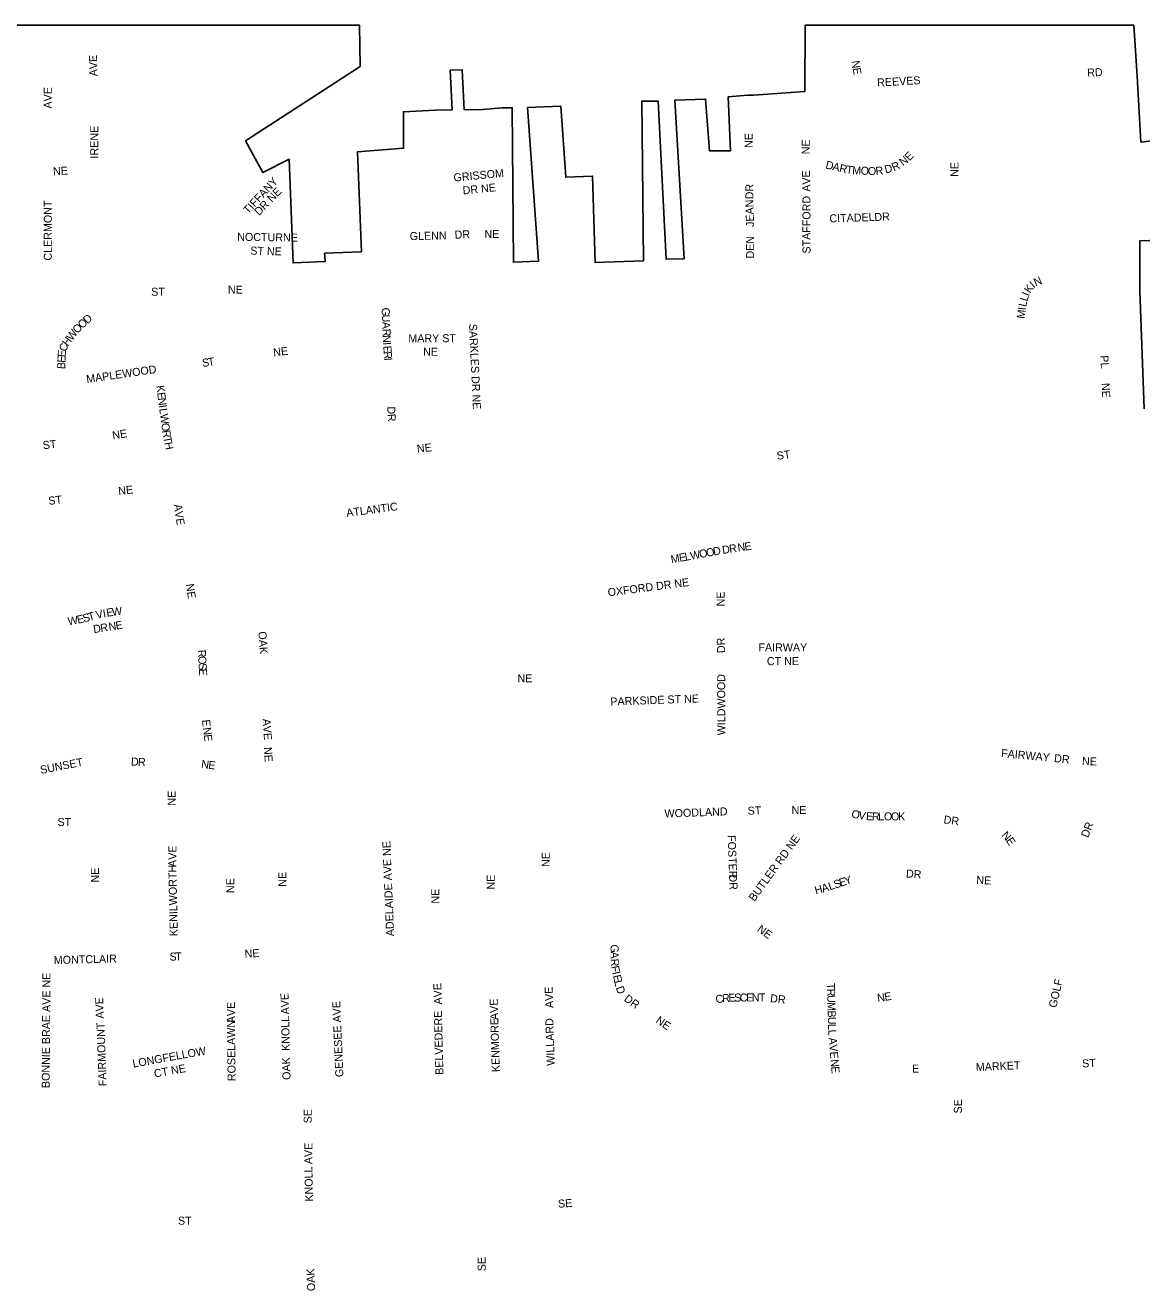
# Model space of a CAD drawing. Extents: x 0 to 34, y -0.1 to 32.4.
# Drawn here: x 4.363 to 5.683, y 30.861 to 32.359 of the extents above; entities that cross this region are included whole.
import ezdxf

# ---------------------------------------------------------------- set-up
doc = ezdxf.new("R2010")
doc.units = 0
doc.layers.add('GM_X_Interchange_Ramps', color=7, linetype='Continuous')
doc.layers.add('GM_X_US_Shield', color=7, linetype='Continuous')

msp = doc.modelspace()

# ---------------------------------------------------------------- linework, layer by layer
at = {"layer": 'GM_X_Interchange_Ramps'}
for p, q in [((4.7582, 32.3588), (4.09, 32.3588)), ((5.6741, 32.3588), (5.2853, 32.3588))]:
    msp.add_line(p, q, dxfattribs=at)
for points in [[(5.2853, 32.3588), (5.2849, 32.2804), (5.2245, 32.2763), (5.2175, 32.2763), (5.1943, 32.2742), (5.197, 32.2104), (5.1723, 32.2104), (5.1676, 32.2716), (5.1312, 32.2703), (5.142, 32.0826), (5.1208, 32.082), (5.1116, 32.269), (5.092, 32.2692), (5.0939, 32.0801), (5.0367, 32.0782), (5.0339, 32.1803), (5.0021, 32.1791), (4.9961, 32.2631), (4.9567, 32.2615), (4.9697, 32.0799), (4.9401, 32.0784), (4.9389, 32.2613), (4.9264, 32.2612), (4.9041, 32.2592), (4.8819, 32.2589), (4.8797, 32.3063), (4.8655, 32.3056), (4.8676, 32.2588), (4.8475, 32.2583), (4.8101, 32.2565), (4.8103, 32.2133), (4.7558, 32.2091), (4.7604, 32.0908), (4.7168, 32.0891), (4.717, 32.0858), (4.7174, 32.0792), (4.6796, 32.0777), (4.6748, 32.2004), (4.6436, 32.1848), (4.6234, 32.2221), (4.759, 32.3101), (4.7582, 32.3588)], [(5.7691, 32.2312), (5.6825, 32.2207), (5.678, 32.2988), (5.6741, 32.3588)], [(5.6863, 31.9049), (5.6813, 32.0448), (5.6813, 32.1036), (5.7604, 32.1065)]]:
    msp.add_lwpolyline(points, dxfattribs=at)

# ---------------------------------------------------------------- texts
at = {"layer": 'GM_X_US_Shield'}
for s, rotation, p in [('AVE', 91.468, (4.4482, 32.2986)), ('N', 278.1363, (5.3401, 32.3164)), ('E', 279.924, (5.3414, 32.3078)), ('REEVES', 3.3023, (5.3707, 32.2863)), ('RD', 3.0116, (5.6191, 32.298)), ('AVE', 90, (4.3941, 32.2603)), ('IRENE', 90, (4.4491, 32.2012)), ('NE', 90, (5.2232, 32.2137)), ('NE', 90, (5.2907, 32.2062)), ('E', 43.7058, (5.4084, 32.1977)), ('D', 346.4779, (5.3088, 32.1896)), ('A', 346.4779, (5.3169, 32.1876)), ('R', 346.4703, (5.325, 32.1857)), ('T', 351.9836, (5.3333, 32.1837)), ('D', 15.3226, (5.3806, 32.1833)), ('R', 24.6002, (5.3902, 32.186)), ('N', 38.2023, (5.4011, 32.1919)), ('NE', 90, (5.4666, 32.1795)), ('NE', 3.011, (4.3958, 32.1813)), ('TIFFANY', 47.0689, (4.6264, 32.1348)), ('GRISSOM', 5.528, (4.8698, 32.1738)), ('AVE', 91.5062, (5.2916, 32.162)), ('M', 357.1643, (5.3408, 32.1827)), ('O', 357.2682, (5.3508, 32.1822)), ('O', 358.2026, (5.3593, 32.1818)), ('R', 6.6567, (5.3691, 32.1816)), ('DR NE', 46.0045, (4.6394, 32.133)), ('DR NE', 5.5717, (4.8806, 32.1586)), ('DR', 90, (5.2241, 32.1529)), ('CLERMONT', 90, (4.3941, 32.0804)), ('JEAN', 91.6837, (5.2249, 32.1203)), ('STAFFORD', 90, (5.2916, 32.0887)), ('CITADEL', 1.9405, (5.3141, 32.1255)), ('DR', 3.011, (5.3674, 32.1271)), ('NOCTURNE', 359.2466, (4.6134, 32.1038)), ('GLENN', 1.1711, (4.8176, 32.1046)), ('DR', 1.9739, (4.8708, 32.1063)), ('NE', 0, (4.9059, 32.1071)), ('DEN', 90, (5.2249, 32.0828)), ('ST NE', 358.4935, (4.6288, 32.0875)), ('N', 23.6119, (5.5581, 32.0497)), ('ST', 0, (4.5117, 32.0388)), ('NE', 0, (4.6025, 32.0413)), ('I', 68.6126, (5.5499, 32.0377)), ('K', 54.7519, (5.5512, 32.041)), ('I', 40.561, (5.5556, 32.0474)), ('L', 77.246, (5.5466, 32.0251)), ('L', 72.8049, (5.548, 32.0315)), ('D', 42.7897, (4.4363, 32.0049)), ('G', 272.2517, (4.7843, 32.0246)), ('U', 272.2526, (4.7846, 32.0163)), ('M', 83.1167, (5.5449, 32.0113)), ('I', 83.1419, (5.5461, 32.0213)), ('W', 52.7686, (4.418, 31.985)), ('O', 45.0464, (4.4243, 31.9934)), ('O', 42.8354, (4.4301, 31.9993)), ('A', 272.2526, (4.785, 32.0079)), ('R', 272.2558, (4.7853, 31.9996)), ('SARKLES DR NE', 272.7012, (4.8876, 32.0054)), ('H', 54.5335, (4.4132, 31.9783)), ('N', 272.4218, (4.7856, 31.9921)), ('I', 273.4139, (4.7859, 31.9836)), ('MARY ST', 0, (4.8159, 31.9838)), ('E', 86.7194, (4.4105, 31.966)), ('C', 67.9145, (4.4107, 31.9719)), ('NE', 6.0054, (4.6565, 31.9671)), ('E', 274.2622, (4.7862, 31.9793)), ('R', 274.412, (4.7867, 31.9726)), ('NE', 0, (4.8334, 31.9677)), ('B', 88.0326, (4.4099, 31.9519)), ('E', 87.349, (4.4102, 31.9594)), ('MAPLEWOOD', 8.3105, (4.4356, 31.9354)), ('S', 5.7595, (4.5724, 31.9546)), ('T', 9.0724, (4.5796, 31.9554)), ('I', 274.4275, (4.7873, 31.9651)), ('PL', 273.5742, (5.6343, 31.968)), ('K', 277.5629, (4.5176, 31.9322)), ('E', 277.5351, (4.5187, 31.924)), ('NE', 273.0113, (5.6359, 31.9354)), ('N', 277.5526, (4.5196, 31.9174)), ('I', 277.5837, (4.5207, 31.9091)), ('L', 277.5622, (4.5212, 31.905)), ('W', 277.5535, (4.5221, 31.8984)), ('D', 270.2841, (4.791, 31.9078)), ('R', 275.2278, (4.7911, 31.8986)), ('NE', 8.9729, (4.4664, 31.8688)), ('O', 277.5412, (4.5235, 31.8876)), ('R', 279.3459, (4.5247, 31.8791)), ('ST', 6.5823, (4.384, 31.8571)), ('T', 280.7822, (4.5259, 31.8714)), ('H', 280.8955, (4.5272, 31.8648)), ('NE', 6.0123, (4.8265, 31.853)), ('ST', 7.598, (5.2523, 31.8446)), ('NE', 6.0123, (4.4732, 31.803)), ('ST', 6.5823, (4.3906, 31.7913)), ('AVE', 278.7466, (4.5384, 31.7915)), ('ATLANTIC', 7.4322, (4.7431, 31.7771)), ('D', 8.988, (5.1878, 31.7332)), ('R', 8.1885, (5.196, 31.7345)), ('N', 8.1356, (5.2059, 31.736)), ('E', 8.1317, (5.2141, 31.7371)), ('M', 10.4295, (5.1272, 31.7221)), ('E', 10.4233, (5.137, 31.7239)), ('L', 10.4367, (5.1436, 31.7251)), ('W', 10.4296, (5.1502, 31.7263)), ('O', 10.429, (5.1608, 31.7283)), ('O', 10.429, (5.169, 31.7298)), ('D', 10.429, (5.1772, 31.7313)), ('OXFORD DR NE', 7.3337, (5.0523, 31.683)), ('NE', 278.9682, (4.5526, 31.6973)), ('NE', 90, (5.1899, 31.6712)), ('E', 8.3754, (4.4593, 31.6589)), ('W', 6.9436, (4.4658, 31.6599)), ('W', 9.5867, (4.4139, 31.6488)), ('E', 12.1119, (4.425, 31.6507)), ('S', 15.1533, (4.4321, 31.6522)), ('T', 15.3055, (4.4385, 31.6539)), ('V', 13.2199, (4.4473, 31.6563)), ('I', 9.5054, (4.4553, 31.6582)), ('E', 8.7347, (4.4703, 31.6437)), ('D', 9.0311, (4.4439, 31.6395)), ('R', 9.0429, (4.4522, 31.6408)), ('N', 9.0096, (4.462, 31.6424)), ('OAK', 273.8119, (4.6385, 31.6413)), ('DR', 91.9739, (5.1907, 31.6161)), ('FAIRWAY', 0, (5.23, 31.618)), ('R', 273.4021, (4.5668, 31.6196)), ('O', 273.4217, (4.5672, 31.6121)), ('CT NE', 0, (5.24, 31.6017)), ('S', 273.4299, (4.5677, 31.6038)), ('E', 273.4299, (4.5681, 31.5972)), ('NE', 0, (4.945, 31.5813)), ('WILDWOOD', 90, (5.1907, 31.5187)), ('PARKSIDE ST NE', 2.0824, (5.055, 31.5538)), ('E', 275.9331, (4.5718, 31.5368)), ('AVE', 273.9431, (4.6435, 31.538)), ('N', 277.0973, (4.5728, 31.5275)), ('E', 277.1167, (4.5738, 31.5192)), ('NE', 273.011, (4.6451, 31.5046)), ('SUNSET', 11.0942, (4.3813, 31.4729)), ('D', 357.7151, (4.4876, 31.483)), ('R', 357.7276, (4.4959, 31.4826)), ('N', 351.8204, (4.5704, 31.4804)), ('FAIRWAY', 354.7255, (5.5168, 31.493)), ('DR', 354.0932, (5.5794, 31.4871)), ('NE', 356.9833, (5.6126, 31.4838)), ('E', 353.0915, (4.5788, 31.4792)), ('NE', 90, (4.5407, 31.4354)), ('WOODLAND', 2.0954, (5.1191, 31.4213)), ('ST', 2.2055, (5.2174, 31.4246)), ('NE', 0, (5.2692, 31.4255)), ('O', 350.2826, (5.3395, 31.4213)), ('V', 350.6716, (5.3478, 31.4199)), ('ST', 0, (4.4009, 31.4113)), ('E', 356.6782, (5.3571, 31.4184)), ('R', 359.9049, (5.3643, 31.418)), ('L', 359.9956, (5.3718, 31.418)), ('O', 359.9929, (5.3785, 31.418)), ('O', 359.9929, (5.3868, 31.418)), ('K', 359.9929, (5.3952, 31.418)), ('DR', 352.1471, (5.4486, 31.4146)), ('DR', 68.7492, (5.62, 31.3968)), ('FOSTER', 272.2014, (5.1935, 31.4004)), ('BUTLER RD NE', 54.059, (5.2253, 31.3214)), ('N', 312.1708, (5.517, 31.4)), ('AVE', 90, (4.5416, 31.3629)), ('ADELAIDE AVE NE', 92.3096, (4.7991, 31.2811)), ('E', 302.7278, (5.5224, 31.3942)), ('NE', 90, (4.9832, 31.3629)), ('NE', 90, (4.4499, 31.3445)), ('KENILWORTH', 91.2313, (4.5432, 31.2811)), ('NE', 90, (4.6716, 31.3395)), ('DR', 356.0537, (5.4043, 31.3505)), ('NE', 90, (4.6099, 31.332)), ('NE', 90, (4.9182, 31.3362)), ('DR', 273.0113, (5.1951, 31.3538)), ('H', 15.0117, (5.2979, 31.3304)), ('A', 16.6185, (5.3062, 31.3326)), ('L', 18.3622, (5.3145, 31.3351)), ('S', 18.4336, (5.3208, 31.3372)), ('E', 18.4479, (5.3272, 31.3393)), ('Y', 18.4349, (5.3335, 31.3414)), ('NE', 356.9884, (5.4876, 31.343)), ('NE', 90, (4.8524, 31.3195)), ('NE', 323.7458, (5.2277, 31.2876)), ('NE', 2.8608, (4.6224, 31.2555)), ('G', 270.1311, (5.0551, 31.2712)), ('MONTCLAIR', 1.3809, (4.3966, 31.248)), ('S', 0.1366, (4.5334, 31.2521)), ('T', 1.789, (4.5403, 31.2522)), ('A', 270.1449, (5.0552, 31.2628)), ('R', 271.9293, (5.0552, 31.2542)), ('BONNIE BRAE AVE NE', 89.6104, (4.3916, 31.1012)), ('F', 280.9398, (5.0556, 31.2451)), ('I', 282.6135, (5.0569, 31.2382)), ('E', 282.6871, (5.0579, 31.2342)), ('AVE', 91.9738, (4.8557, 31.2003)), ('AVE', 91.9739, (4.9874, 31.1961)), ('L', 282.6977, (5.0593, 31.2277)), ('D', 289.5421, (5.0611, 31.22)), ('T', 271.6393, (5.311, 31.2254)), ('GOLF', 77.1199, (5.5824, 31.1957)), ('AVE', 91.9739, (4.4557, 31.1836)), ('AVE', 91.9738, (4.6749, 31.1886)), ('AVE', 91.9739, (4.9224, 31.182)), ('DR', 323.7481, (5.0702, 31.2051)), ('C', 11.8386, (5.1803, 31.2012)), ('R', 4.205, (5.1873, 31.2027)), ('E', 2.3916, (5.1947, 31.2033)), ('S', 1.8036, (5.2014, 31.2035)), ('C', 0.3765, (5.208, 31.2037)), ('E', 0.0137, (5.2155, 31.2038)), ('N', 0, (5.2221, 31.2038)), ('T', 0, (5.2305, 31.2038)), ('DR', 353.9877, (5.2435, 31.203)), ('R', 271.6272, (5.3112, 31.2187)), ('U', 271.6175, (5.3114, 31.2112)), ('N', 8.5243, (5.3712, 31.203)), ('E', 9.9675, (5.3797, 31.2043)), ('AVE', 90, (4.6107, 31.1779)), ('GENESEE AVE', 92.4376, (4.7391, 31.1144)), ('BELVEDERE', 91.4137, (4.8574, 31.117)), ('M', 271.6214, (5.3116, 31.2029)), ('B', 271.6265, (5.3119, 31.1929)), ('FAIRMOUNT', 92.0689, (4.4591, 31.1036)), ('ROSELAWN', 90.7437, (4.6116, 31.1095)), ('KNOLL', 91.2182, (4.6757, 31.1453)), ('KENMORE', 91.6625, (4.9241, 31.1203)), ('WILLARD', 91.7889, (4.9891, 31.1278)), ('NE', 325.4857, (5.1077, 31.1793)), ('U', 271.6326, (5.3121, 31.1854)), ('L', 271.612, (5.3123, 31.1771)), ('L', 273.0167, (5.3125, 31.1702)), ('A', 274.7917, (5.3131, 31.1607)), ('LONGFELLOW', 10.2515, (4.4905, 31.1254)), ('V', 274.8364, (5.3138, 31.1524)), ('CT NE', 10.1751, (4.5159, 31.1136)), ('OAK', 91.9082, (4.6766, 31.1111)), ('E', 274.8442, (5.3145, 31.1441)), ('N', 274.8363, (5.3153, 31.1349)), ('MARKET', 2.4898, (5.4874, 31.1213)), ('ST', 3.5746, (5.6132, 31.1255)), ('E', 274.863, (5.316, 31.1266)), ('E', 0, (5.4117, 31.1196)), ('SE', 90, (5.4707, 31.0712)), ('SE', 90, (4.7016, 31.0595)), ('AVE', 90, (4.7024, 31.0112)), ('KNOLL', 91.2229, (4.7032, 30.967)), ('SE', 3.5738, (4.9932, 30.9596)), ('ST', 0, (4.5434, 30.9396)), ('SE', 90, (4.9074, 30.8845)), ('OAK', 91.9081, (4.7057, 30.8611))]:
    msp.add_text(s, height=0.00947, rotation=rotation, dxfattribs=at).set_placement(p)

doc.saveas('drawing.dxf')
